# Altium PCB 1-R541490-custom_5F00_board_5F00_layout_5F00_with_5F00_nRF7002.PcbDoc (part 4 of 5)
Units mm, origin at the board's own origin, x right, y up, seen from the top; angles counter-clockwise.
Board outline 180 x 80 mm, 6 copper layers (Top Layer, GND 1, Signal 1, POWER, GND 2, Bottom Layer), stack 1.609 mm thick; 321 components, 275 nets, 828 pads, 1164 vias.
Unrouted connection lines stored in the file: 746.
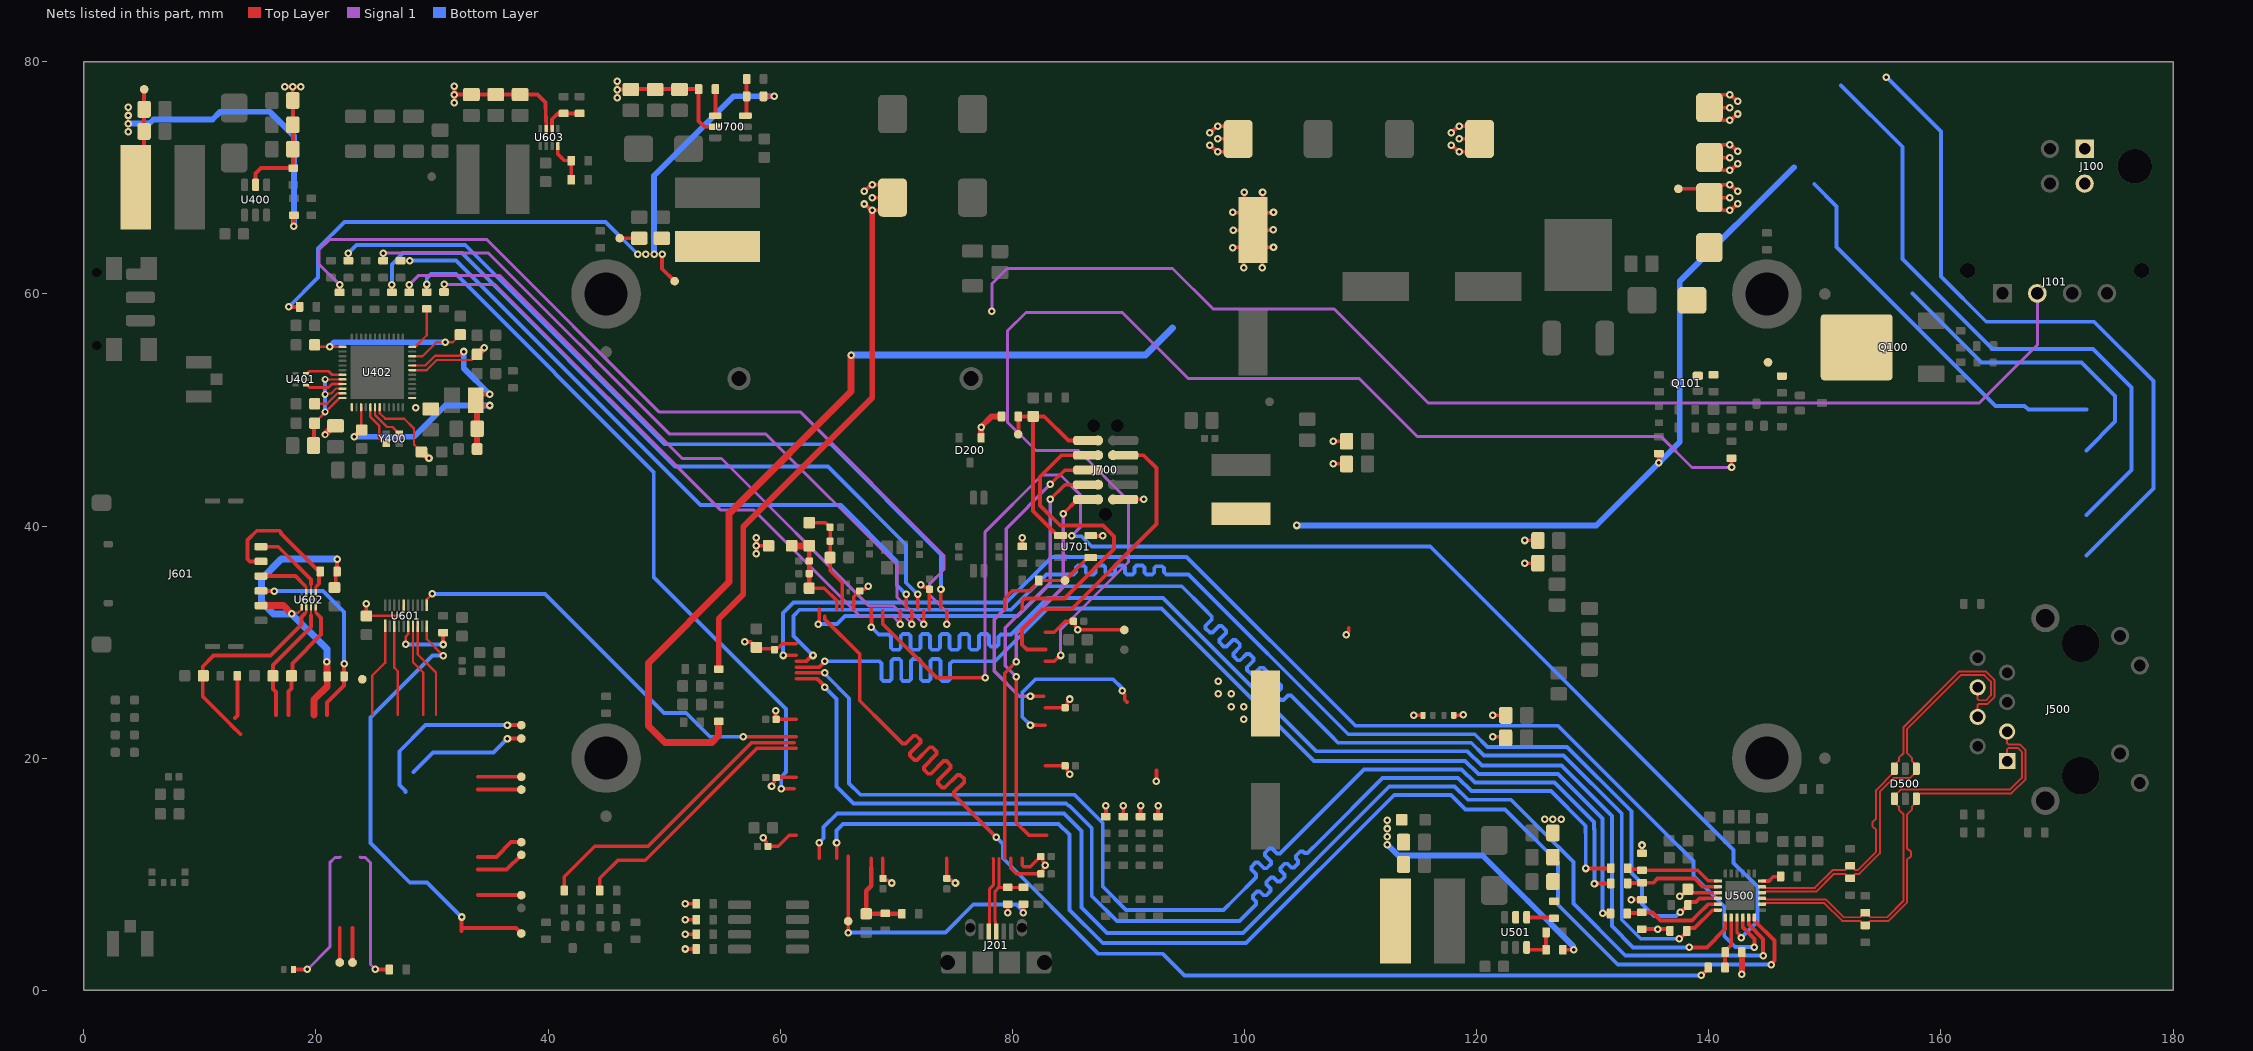
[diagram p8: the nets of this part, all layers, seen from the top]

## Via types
v1: diameter 0.65, hole 0.3, Top Layer to Bottom Layer, tented both sides, 675 vias
v2: diameter 0.7, hole 0.3, Top Layer to Bottom Layer, tented both sides, 462 vias
v3: diameter 0.6, hole 0.3, Top Layer to Bottom Layer, 16 vias
v4: diameter 0.6, hole 0.3, Top Layer to Bottom Layer, tented both sides, 7 vias
v5: diameter 0.6, hole 0.3, Top Layer to Bottom Layer, tented bottom, 4 vias

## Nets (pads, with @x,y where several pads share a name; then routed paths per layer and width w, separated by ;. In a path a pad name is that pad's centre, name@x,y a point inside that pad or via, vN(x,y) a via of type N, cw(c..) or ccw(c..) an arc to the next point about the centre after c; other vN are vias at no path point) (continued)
NetR416_1: R416.1 U402.36 | length 3.9
  Top Layer w0.2: U402.36@28.294,55.437 28.544,55.437 29.544,56.437 R416.1@29.544,58.712
NetR501_1: R501.1 R511.2 U500.11 | length 8.7
  Top Layer w0.3: 139.923,7.422 U500.11@140.778,7.422
  Top Layer w0.335: R511.2@132.978,6.622 133.028,6.672 134.168,6.672 R501.1@134.218,6.722 135.148,6.722 135.848,6.022 138.54,6.022 139.073,6.555 139.923,7.405
NetR502_1: R502.1 R508.2 U500.8 | length 8.2
  Top Layer w0.3: 139.487,8.923 U500.8@140.778,8.923
  Top Layer w0.335: R508.2@133.003,9.222 133.028,9.247 134.218,9.247 R502.1@134.243,9.273 135.225,9.273 135.575,9.622 138.787,9.622 139.469,8.94 139.487,8.94
NetR503_1: R503.1 R509.2 U500.7 | length 8.2
  Top Layer w0.3: 139.045,10.347 139.966,9.427 U500.7@140.773,9.427
  Top Layer w0.335: R509.2@133.003,10.522 133.003,10.505 133.073,10.435 134.156,10.435 R503.1@134.243,10.347 139.045,10.347
NetR510_2: R510.2 R512.1 U500.14 | length 4.6
  Top Layer w0.3: R512.1@141.395,1.86 R512.1@141.395,1.96 R512.1@141.4,1.965 ; R510.2@141.4,3.285 R510.2@141.405,3.29 R510.2@141.405,3.39 ; 141.928,3.913 U500.14@141.928,6.273
  Top Layer w0.335: R512.1@141.4,1.965 R510.2@141.4,3.285 ; R510.2@141.405,3.39 141.928,3.913
NetR513_2: R513.2 U500.24 | length 1.8
  Top Layer w0.335: U500.24@144.578,9.423 145.178,9.423 145.547,9.791 146.147,9.791 R513.2@146.178,9.822
NetR516_1: R516.1 U501.4 | length 2.4
  Top Layer w0.335: U501.4@124.309,6.35 124.375,6.285 126.602,6.285 R516.1@126.667,6.219
NetR517_1: R517.1 R520.2 U501.3 | length 3.3
  Top Layer w0.335: U501.3@124.338,3.621 124.309,3.65 124.309,3.632 124.442,3.5 R517.1@125.975,3.5 R520.2@125.975,5
NetR600_1: R600.1 | length 12.3
  Top Layer w0.335: R600.1@18.075,1.8 v1(19.271,1.8)
  Signal 1 w0.256: v1(19.271,1.8) 21.2,3.729 21.2,11 21.648,11.448 22.052,11.448 22.1,11.496
NetR602_2: R602.2 | length 3.8
  Top Layer w0.335: 13.018,23.45 13.25,23.683 13.238,23.695 13.238,27.087 R602.2@13.225,27.1
NetR603_2: R603.2 | length 11.7
  Top Layer w0.335: v1(25.129,1.8) R603.2@26.325,1.8
  Signal 1 w0.256: 23.8,11.496 23.86,11.436 24.264,11.436 24.7,11 24.7,2.229 v1(25.129,1.8)
NetR606_1: R606.1 U601.6 | length 5.8
  Top Layer w0.2: v1(27.75,29.8) 27.75,30.49 27.96,30.7 U601.6@27.96,31.37
  Top Layer w0.335: v1(30.96,29.797) R606.1@30.96,30.721
  Bottom Layer w0.335: v1(27.75,29.8) 27.752,29.798 30.959,29.798 v1(30.96,29.797)
NetR613_1: R613.1 R616.2 U603.8 | length 3.7
  Top Layer w0.3: U603.8@40.844,72.736 40.844,72.05 41.4,71.494 41.976,71.494 R616.2@41.994,71.476 R613.1@41.994,69.836
NetR614_1: R614.1 R615.2 U603.2 | length 3.4
  Top Layer w0.335: U603.2@40.344,74.216 40.344,75.051 40.844,75.551 R615.2@41.338,75.551 R614.1@42.719,75.551
NetR718_1: R718.1 U700.4 | length 2.3
  Top Layer w0.335: U700.4@54.35,75.35 54.415,75.415 R718.1@54.415,77.643
NetR719_1: R719.1 R722.2 U700.3 | length 3.2
  Top Layer w0.335: U700.3@57.05,75.35 57.079,75.379 57.079,78.494 R722.2@57.108,78.523
NetR821_1: 
NetR822_2: 
NetTP600_1: TP600.1 | length 3.7
  Top Layer w0.335: 33.975,8.2 TP600.1@37.7,8.2
NetTP603_1: TP603.1
NetTP604_1: TP604.1 | length 3.7
  Top Layer w0.335: 33.975,18.4 TP604.1@37.7,18.4
NetTP605_1: TP605.1 | length 3.7
  Top Layer w0.335: 33.975,17.3 TP605.1@37.7,17.3
NetTP606_1: TP606.1 | length 3
  Top Layer w0.335: TP606.1@23.15,2.4 23.15,5.37
NetTP607_1: TP607.1 | length 3
  Top Layer w0.335: TP607.1@22.05,2.4 22.05,5.37
NetTP608_1: TP608.1 | length 4.3
  Top Layer w0.335: 33.975,11.5 35.557,11.5 36.822,12.765 37.692,12.765 TP608.1@37.7,12.773
NetTP609_1: TP609.1 | length 4.3
  Top Layer w0.335: 33.975,10.4 36.427,10.4 TP609.1@37.7,11.673
NetTP610_1: TP610.1 | length 15.1
  Top Layer w0.335: v1(36.504,22.85) TP610.1@37.7,22.85
  Bottom Layer w0.335: 27.704,17.1 27.704,17.185 27.2,17.689 27.2,20.598 29.452,22.85 v1(36.504,22.85)
NetTP611_1: TP611.1 | length 10.5
  Top Layer w0.335: v1(36.504,21.696) TP611.1@37.7,21.696
  Bottom Layer w0.335: 28.396,18.8 30.096,20.5 35.308,20.5 v1(36.504,21.696)
NetU402_17: U402.17 Y400.3 | length 3.8
  Top Layer w0.2: U402.17@24.694,50.237 24.694,49.395 25.469,48.621 25.469,47.559 25.765,47.263 25.869,47.263 Y400.3@26.044,47.088
NetU402_18: U402.18 Y400.1 | length 3.4
  Top Layer w0.2: U402.18@25.094,50.237 25.094,49.561 26.118,48.537 26.594,48.537 Y400.1@27.194,47.937
nRST: C701.2 J700.10 R716.1 TP202.1 U500.15 U701.1 | length 138.7
  Top Layer w0.3: 68.85,32.699 68.85,31.561 73.461,26.95 v1(77.658,26.95) ; U500.15@142.428,6.273 142.428,5.017 142.8,4.645 v1(142.8,4.55)
  Top Layer w0.335: TP202.1@80.513,47.9 80.513,49.435 R716.1@80.515,49.437 ; R716.1@80.523,49.442 C701.2@81.792,49.442 ; C701.2@81.8,49.437 81.779,49.416 81.779,41.292 83.764,39.307 84.001,39.307 U701.1@84.141,39.167 ; C701.2@81.808,49.442 82.746,49.442 84.827,47.361 J700.10@86.257,47.361 ; U701.1@84.149,39.175 84.161,39.162 85.087,39.162 v1@85.107,39.142
  Signal 1 w0.256: v1(77.658,26.95) 77.658,39.508 82.55,44.4 84.15,44.4 85.857,42.693 85.857,39.893 v1(85.115,39.15)
  Bottom Layer w0.335: v1(85.115,39.15) 85.14,39.125 85.942,39.125 86.842,38.225 116.001,38.225 142.128,12.098 142.128,10.986 144.178,8.936 144.178,5.928 v1(142.8,4.55)
NTC: J101.2 | length 104.3
  Top Layer w0.335: v1(78.225,58.521) v1@78.236,58.521
  Signal 1 w0.256: v1(78.225,58.521) 78.225,60.861 79.564,62.2 93.8,62.2 97.3,58.7 107.721,58.7 115.821,50.6 163.3,50.6 168.3,55.6 J101.2@168.3,60.05
OFF_bt: R119.2 | length 107.8
  Top Layer w0.3: 82.838,28.35 83.606,28.35 84.106,28.85 v1(84.161,28.85)
  Top Layer w0.335: v1@141.958,45.05 R119.2@141.958,45.849
  Signal 1 w0.256: v1(84.161,28.85) 84.151,28.86 84.151,31.051 90,36.9 90,42.189 85.689,46.5 82.036,46.5 79.564,48.972 79.564,56.797 81.167,58.4 89.47,58.4 95.17,52.7 109.9,52.7 114.904,47.696 135.9,47.696 138.549,45.048 v1(141.956,45.048)
OUT1+:  | length 54
  Bottom Layer w0.335: 151.403,77.967 156.694,72.676 156.694,63.006 164.45,55.25 173.1,55.25 176.4,51.95 176.4,44.825 172.525,40.95
OUT1-:  | length 58.6
  Bottom Layer w0.335: v1@155.3,78.7 160,74 160,61.5 163.9,57.6 173.2,57.6 178.3,52.5 178.3,43.225 172.525,37.45
  other v1: 155.285,78.685
OUT2+:  | length 33.5
  Bottom Layer w0.335: 149.085,69.455 151,67.54 151,64.048 164.704,50.344 167.206,50.344 167.525,50.026 172.525,50.026
OUT2-:  | length 26.8
  Bottom Layer w0.335: 157.543,60.044 163.486,54.1 172.1,54.1 175,51.2 175,49.001 172.525,46.526
PALDO: C416.2 C417.2 U402.8 U402.10 U402.12 | length 11.3
  Top Layer w0.17: v4(20.794,51.337) 20.876,51.42 21.302,51.42 21.719,51.837 U402.10@22.294,51.837 ; v4(20.794,52.637) U402.8@22.294,52.637
  Top Layer w0.2: C416.2@19.894,48.837 19.894,48.894 20.794,49.794 v4(20.794,49.837) 20.836,49.837 22.036,51.037 U402.12@22.294,51.037
  Top Layer w0.335: C417.2@19.794,46.937 19.844,46.987 19.844,48.787 C416.2@19.894,48.837
  Bottom Layer w0.335: v4(20.794,49.837) v4(20.794,51.337) v4(20.794,52.637)
PVDD: C302.1 C304.2 C305.2 C306.2 C307.2 C308.2 C309.2 L300.2 | length 6.9
  Top Layer w0.3: v1(107.652,45.35) C308.2@108.79,45.35 ; v1(107.652,47.3) C307.2@108.79,47.3 ; v1(121.369,21.863) 122.386,21.863 C305.2@122.491,21.757 ; v1(121.369,23.69) C306.2@122.507,23.69 ; v1(124.137,36.803) C309.2@125.275,36.803 ; v1(124.137,38.757) C304.2@125.275,38.757
  other v1: 99.95,23.35 98.85,24.45 99.95,24.45 97.75,25.55 98.85,25.55 97.75,26.65
PWRIOVDD: C407.2 C410.2 U402.1 U402.34 | length 17.5
  Top Layer w0.2: C407.2@19.894,55.612 20.069,55.437 v1(21.182,55.437) U402.1@22.294,55.437 ; U402.34@28.294,54.637 29.178,54.637 30.378,55.837 v1(31.144,55.837) 31.794,55.837 32.044,56.087 32.044,56.089 C410.2@32.444,56.487 C410.2@32.444,56.487
  Bottom Layer w0.5: v1(21.182,55.437) 21.582,55.837 v1(31.144,55.837)
PWRKEY: R609.1 | length 22.6
  Top Layer w0.3: R609.1@44.451,8.6 44.451,9.65 46.024,11.223 48.37,11.223 57.997,20.85 61.362,20.85
QSPI_CLK/SPI_CLK: R405.2 | length 53.2
  Top Layer w0.2: R405.2@31.044,60.166 R405.2@31.046,60.164 v1(31.046,60.814)
  Top Layer w0.3: v1(70.35,31.561) 70.35,32.699
  Signal 1 w0.256: v1(31.046,60.814) 35.426,60.814 54.84,41.4 57.7,41.4 66.9,32.2 69.711,32.2 v1(70.35,31.561)
QSPI_DATA0/SPI_MOSI: R411.2 | length 57.9
  Top Layer w0.2: R411.2@28.044,60.137 v1(28.044,60.787)
  Top Layer w0.3: v1(71.35,31.561) 71.35,32.699
  Signal 1 w0.256: v1(28.044,60.787) 28.856,61.6 35.79,61.6 51.56,45.83 54.945,45.83 67.675,33.1 69.811,33.1 v1(71.35,31.561)
QSPI_DATA1/SPI_MISO: R415.2 | length 57.8
  Top Layer w0.2: R415.2@27.294,62.862 v1(28.094,62.862)
  Top Layer w0.3: 70.85,32.977 v1(70.85,34.115)
  Bottom Layer w0.335: v1(28.094,62.862) 32.073,62.862 53.136,41.8 65.229,41.8 70.038,36.991 70.038,34.927 v1(70.85,34.115)
QSPI_DATA2: R410.2 | length 63.3
  Top Layer w0.2: R410.2@26.544,60.137 v1(26.544,60.787)
  Top Layer w0.3: 71.85,32.977 v1(71.85,34.115)
  Bottom Layer w0.335: v1(26.544,60.787) 26.544,62.544 27.512,63.512 32.569,63.512 50.946,45.135 64.109,45.135 70.85,38.394 70.85,35.115 v1(71.85,34.115)
QSPI_DATA3: R414.2 | length 63.2
  Top Layer w0.2: R414.2@25.794,62.862 v1(25.794,63.512)
  Top Layer w0.3: v1(72.35,31.561) 72.35,32.699
  Signal 1 w0.256: v1(25.794,63.512) 34.868,63.512 50.43,47.95 58.742,47.95 70.053,36.639 70.053,33.858 v1(72.35,31.561)
QSPI_SS/SPI_SS: R416.2 | length 61.3
  Top Layer w0.2: R416.2@29.544,60.162 v1(29.544,60.812)
  Top Layer w0.3: v1(60.085,17.35) 61.223,17.35
  Bottom Layer w0.335: v1(29.544,60.812) 29.544,61.344 29.9,61.7 32.07,61.7 49.1,44.67 49.1,35.625 60.5,24.225 60.5,18.816 60.085,18.401 v1(60.085,17.35)
R1: U601.1 | length 8.1
  Top Layer w0.2: 24.85,23.73 24.85,27.115 25.96,28.225 U601.1@25.96,31.42
RD_N: D500.4 J500.6 R504.2 U500.22 | length 38
  Top Layer w0.17: U500.22@144.578,8.423 144.643,8.487 144.918,8.487 144.943,8.513 149.261,8.513 150.786,10.037 151.739,10.037 151.846,9.93 151.846,9.887 152.085,9.647 R504.2@152.178,9.647 152.271,9.647 152.51,9.887 152.51,9.93 152.618,10.037 152.974,10.037 154.73,11.793 154.73,17.113 155.932,18.315 157.346,18.315 157.881,18.85 D500.4@157.881,19.1 157.881,19.385 157.493,19.774 157.493,20.034 157.092,20.434 157.092,22.532 161.717,27.157 163.743,27.157 164.3,26.6 164.3,25.41 163.885,24.995 163.26,24.995 163.16,25.095 J500.6@163.16,26.105
RD_P: D500.6 J500.4 R505.2 U500.23 | length 37.9
  Top Layer w0.17: U500.23@144.578,8.923 144.643,8.858 144.918,8.858 144.943,8.832 149.128,8.832 150.653,10.357 151.739,10.357 151.846,10.465 151.846,10.508 152.085,10.747 R505.2@152.178,10.747 152.271,10.747 152.51,10.508 152.51,10.465 152.618,10.357 152.842,10.357 154.41,11.926 154.41,13.754 154.41,13.839 154.274,13.975 154.243,13.975 154.107,14.111 154.107,14.517 154.243,14.653 154.274,14.653 154.41,14.789 154.41,15.46 154.41,17.245 155.981,18.816 D500.6@155.981,19.1 155.981,19.385 156.373,19.777 156.373,20.034 156.772,20.433 156.772,22.665 161.585,27.477 163.875,27.477 164.62,26.733 164.62,25.277 164.018,24.675 163.26,24.675 163.16,24.575 J500.4@163.16,23.565
RESET_N: R607.1 | length 25.8
  Top Layer w0.3: R607.1@41.401,8.6 41.401,9.773 44.028,12.4 48.613,12.4 57.563,21.35 61.223,21.35
RMII_CRS_DV: R511.1 | length 101
  Top Layer w0.3: 61.362,27.85 63.333,27.85 63.35,27.867
  Top Layer w0.335: 63.35,27.867 63.367,27.867 v1(63.85,28.35) ; v1(130.85,6.65) 130.864,6.636 131.514,6.636 R511.1@131.528,6.622
  Bottom Layer w0.335: v1@63.854,28.35 67.532,28.35 68.542,28.35 68.738,28.154 68.738,26.824 68.907,26.656 69.412,26.656 69.581,26.824 69.581,28.373 69.749,28.541 70.255,28.541 70.424,28.373 70.424,26.824 70.592,26.656 71.098,26.656 71.266,26.824 71.266,28.373 71.435,28.541 71.941,28.541 72.109,28.373 72.109,26.824 72.278,26.656 72.783,26.656 72.952,26.824 72.952,28.373 73.121,28.541 73.626,28.541 73.795,28.373 73.795,26.824 73.963,26.656 74.469,26.656 74.638,26.824 74.638,28.154 74.834,28.35 77.87,28.35 78.5,28.35 83.05,32.9 92.852,32.9 105.981,19.772 119.011,19.772 120.153,18.63 127.013,18.63 130.85,14.793 v1(130.85,6.65)
RMII_MDC: U500.13 | length 109.6
  Top Layer w0.3: 67.85,32 67.85,32.838 ; 141.411,5.278 141.428,5.296 U500.13@141.428,6.273
  Top Layer w0.335: v1(67.85,31.3) 67.85,32 ; v1(138.3,3.7) 139.833,3.7 141.411,5.278
  Bottom Layer w0.335: v1(67.85,31.3) 68.336,30.814 68.5,30.65 69.347,30.65 69.543,30.454 69.543,29.514 69.711,29.345 70.217,29.345 70.386,29.514 70.386,30.533 70.554,30.702 71.06,30.702 71.228,30.533 71.228,29.514 71.397,29.345 71.903,29.345 72.071,29.514 72.071,30.533 72.24,30.702 72.745,30.702 72.914,30.533 72.914,29.514 73.082,29.345 73.588,29.345 73.757,29.514 73.757,30.533 73.925,30.702 74.431,30.702 74.6,30.533 74.6,29.514 74.768,29.345 75.274,29.345 75.442,29.514 75.442,30.533 75.611,30.702 76.117,30.702 76.285,30.533 76.285,29.514 76.454,29.345 76.959,29.345 77.128,29.514 77.128,30.533 77.296,30.702 77.802,30.702 77.971,30.533 77.971,29.787 78.139,29.618 78.645,29.618 78.813,29.787 78.813,30.454 79.01,30.65 79.192,30.65 79.889,30.65 83.039,33.8 92.992,33.8 106.196,20.596 119.226,20.596 120.457,19.365 127.318,19.365 131.65,15.033 131.65,5.534 133.484,3.7 v1(138.3,3.7)
RMII_MDIO: R500.2 U500.12 | length 109.7
  Top Layer w0.3: v1(63.28,31.56) 63.28,31.655 63.35,31.725 63.35,32.838 ; 140.308,6.905 140.325,6.923 U500.12@140.778,6.923
  Top Layer w0.335: v1(137.45,4.45) 137.531,4.45 138.103,5.022 R500.2@138.103,5.122 ; R500.2@138.103,5.222 138.261,5.38 138.783,5.38 140.308,6.905
  Bottom Layer w0.335: v1(63.28,31.56) 64.889,31.56 65.579,32.25 67.56,32.25 67.563,32.253 76.637,32.253 76.64,32.25 80.45,32.25 83.011,34.811 94.589,34.811 96.465,32.935 97.179,32.22 97.179,31.943 96.653,31.417 96.653,31.178 97.01,30.821 97.249,30.821 97.802,31.374 98.041,31.374 98.398,31.017 98.398,30.778 97.844,30.225 97.844,29.986 98.202,29.629 98.44,29.629 98.994,30.182 99.232,30.182 99.59,29.825 99.59,29.586 99.036,29.033 99.036,28.794 99.394,28.437 99.632,28.437 100.186,28.99 100.424,28.99 100.782,28.633 100.782,28.395 100.228,27.841 100.228,27.603 100.586,27.245 100.824,27.245 101.378,27.799 101.616,27.799 101.974,27.441 101.974,27.203 101.42,26.649 101.42,26.411 101.778,26.053 102.016,26.053 102.57,26.607 102.808,26.607 103.166,26.249 103.166,26.011 102.769,25.614 102.769,25.375 103.126,25.018 103.365,25.018 103.735,25.388 104.012,25.388 107.373,22.026 108.069,21.33 119.53,21.33 120.626,20.235 127.487,20.235 132.5,15.222 132.5,6.084 134.134,4.45 v1(137.45,4.45)
RMII_REF_CLK: R512.2 | length 104.7
  Top Layer w0.3: 63.85,31.975 63.85,32.225
  Top Layer w0.335: 63.867,31.975 63.867,31.957 66.85,28.975 66.85,24.95 69.2,22.6 70.537,21.263 70.814,21.263 71.484,21.933 71.722,21.933 72.08,21.576 72.08,21.337 71.194,20.452 71.194,20.213 71.552,19.856 71.79,19.856 72.88,20.945 73.118,20.945 73.476,20.588 73.476,20.349 72.386,19.26 72.386,19.021 72.744,18.664 72.982,18.664 74.072,19.753 74.31,19.753 74.667,19.396 74.667,19.157 73.578,18.068 73.578,17.829 73.936,17.472 74.174,17.472 75.263,18.561 75.502,18.561 75.859,18.204 75.859,17.965 74.986,17.092 74.986,16.814 75.7,16.1 v1(78.6,13.2) ; v1(139.34,1.29) 139.375,1.29 139.945,1.86 R512.2@139.945,1.96
  Bottom Layer w0.335: v1(78.6,13.2) 79.192,12.608 79.192,11.378 87.42,3.15 92.96,3.15 94.82,1.29 v1(139.34,1.29)
RMII_RX_ER: R514.2 U500.10 | length 109.5
  Top Layer w0.3: 61.362,28.35 62.24,28.35 ; 139.666,7.923 U500.10@140.778,7.923
  Top Layer w0.335: 62.275,28.385 62.74,28.85 v1(62.825,28.85) ; v1(137.531,6.722) 137.592,6.722 137.96,7.09 138.046,7.09 138.203,7.248 R514.2@138.203,7.333 ; R514.2@138.203,7.448 138.361,7.605 138.879,7.605 139.179,7.905 139.666,7.905
  Bottom Layer w0.335: v1(62.825,28.85) 61.138,30.537 61.138,32.25 61.676,32.788 79.888,32.788 82.938,35.838 85.115,35.838 85.282,35.838 85.478,36.034 85.478,36.438 85.647,36.607 86.152,36.607 86.321,36.438 86.321,35.989 86.49,35.82 86.995,35.82 87.164,35.989 87.164,36.438 87.332,36.607 87.838,36.607 88.007,36.438 88.007,35.989 88.175,35.82 88.681,35.82 88.849,35.989 88.849,36.438 89.018,36.607 89.524,36.607 89.692,36.438 89.692,35.989 89.861,35.82 90.366,35.82 90.535,35.989 90.535,36.438 90.704,36.607 91.209,36.607 91.378,36.438 91.378,35.989 91.546,35.82 92.052,35.82 92.221,35.989 92.221,36.373 92.389,36.542 92.895,36.542 93.063,36.373 93.063,36.034 93.259,35.838 94.434,35.838 95.162,35.838 108.935,22.065 119.835,22.065 120.929,20.971 127.79,20.971 133.329,15.432 133.329,10.114 134.243,9.2 134.243,7.437 135.28,6.4 137.177,6.4 137.499,6.722 v1(137.531,6.722)
RMII_RXD0: R508.1 | length 101.5
  Top Layer w0.3: 61.362,27.35 v1(63.85,27.35)
  Top Layer w0.335: v1(130.15,9.2) 130.161,9.211 131.542,9.211 R508.1@131.553,9.222
  Bottom Layer w0.335: v1(63.85,27.35) 63.85,27.265 64.008,27.107 64.008,27.101 65.939,25.169 65.939,17.811 66.9,16.85 85.35,16.85 87.782,14.418 87.782,8.955 89.801,6.936 98.197,6.936 99.113,7.852 100.994,9.732 100.994,10.009 100.59,10.412 100.59,10.651 100.948,11.008 101.186,11.008 101.678,10.517 101.916,10.517 102.274,10.874 102.274,11.113 101.772,11.614 101.772,11.853 102.13,12.21 102.368,12.21 102.781,11.797 103.059,11.797 103.773,12.512 110.298,19.037 118.706,19.037 119.848,17.895 126.709,17.895 130.115,14.489 130.115,13.882 ; v1(130.15,9.2) 130.15,13.867
RMII_RXD1: R509.1 | length 101.5
  Top Layer w0.3: 61.362,26.85 63.168,26.85 63.185,26.833
  Top Layer w0.335: 63.185,26.833 63.203,26.833 63.85,26.185 v1(63.85,26.1) ; v1(129.4,10.5) 129.411,10.511 131.542,10.511 R509.1@131.553,10.522
  Bottom Layer w0.335: v1(63.85,26.1) 64.85,25.1 64.85,17.576 66.311,16.115 84.624,16.115 84.832,15.907 84.914,15.907 86.842,13.979 86.842,8.145 89.027,5.96 99.56,5.96 100.865,7.265 100.984,7.384 100.984,7.661 100.715,7.929 100.715,8.168 101.073,8.525 101.311,8.525 101.643,8.194 101.881,8.194 102.239,8.551 102.239,8.79 101.907,9.121 101.907,9.36 102.265,9.717 102.503,9.717 102.835,9.386 103.073,9.386 103.43,9.743 103.43,9.982 103.099,10.313 103.099,10.551 103.456,10.909 103.695,10.909 104.026,10.577 104.265,10.577 104.622,10.935 104.622,11.173 104.439,11.356 104.439,11.595 104.797,11.952 105.035,11.952 105.155,11.832 105.432,11.832 106.57,12.97 111.902,18.302 118.402,18.302 119.544,17.16 126.405,17.16 129.38,14.185 129.38,13.578 129.4,13.558 v1(129.4,10.5)
RMII_TX_EN: U500.16 | length 109.6
  Top Layer w0.3: v1(60.27,28.85) 61.362,28.85 ; U500.16@142.928,6.273 142.928,5.445 142.949,5.424 142.949,5.399
  Top Layer w0.335: 142.949,5.399 143.928,4.42 v1(143.928,3.722)
  Bottom Layer w0.335: v1(60.27,28.85) 60.224,28.896 60.224,32.508 61.138,33.423 79.473,33.423 83.4,37.35 95.005,37.35 109.555,22.8 120.997,22.8 121,22.797 121.739,22.797 121.742,22.8 127,22.8 136.009,13.791 136.026,13.791 138.676,11.141 138.676,9.875 141.327,7.224 141.327,4.673 142.278,3.722 v1(143.928,3.722)
RMII_TXD0: U500.17 | length 109.6
  Top Layer w0.3: 63.35,11.362 v1(63.35,12.713) ; 143.428,5.677 143.428,6.029 U500.17@143.428,6.273
  Top Layer w0.335: 143.446,5.677 143.446,5.659 144.678,4.427 v1(144.678,2.997)
  Bottom Layer w0.335: v1(63.35,12.713) 63.741,13.104 63.741,14.081 64.91,15.25 84.45,15.25 85.971,13.729 85.971,7.129 88.15,4.95 99.855,4.95 112.473,17.567 118.098,17.567 119.239,16.426 122.949,16.426 124.975,14.4 124.975,14.375 125.498,13.852 125.523,13.852 128.328,11.047 128.328,7.472 132.803,2.997 v1(144.678,2.997)
RMII_TXD1: U500.18 | length 109.6
  Top Layer w0.3: 64.85,11.362 v1(64.85,12.713) ; U500.18@143.928,6.273 143.928,6.032 U500.18@143.946,6.015
  Top Layer w0.335: U500.18@143.946,5.998 145.643,4.3 145.643,2.573 145.378,2.308 v1(145.378,2.222)
  Bottom Layer w0.335: v1(64.85,12.713) 64.85,13.774 65.418,14.342 83.99,14.342 84.914,13.418 84.914,6.936 87.782,4.068 100.139,4.068 112.904,16.833 117.793,16.833 119.028,15.598 122.442,15.598 127,11.04 127,7.38 132.158,2.222 v1(145.378,2.222)
RTS: U601.3 | length 7.8
  Top Layer w0.2: U601.3@26.76,31.37 26.76,27.79 27.05,27.5 27.05,23.73
RXD: U601.8 | length 8.3
  Top Layer w0.2: U601.8@28.76,31.37 28.76,28.965 30.35,27.375 30.35,23.73
SIM_C_CLK: J601.C3 U602.2 | length 6.6
  Top Layer w0.2: 19.568,35.012 19.568,35.007 19.575,35 U602.2@19.575,34.292
  Top Layer w0.335: J601.C3@15.265,38.225 15.27,38.22 16.755,38.22 19.575,35.4 19.575,35.02
SIM_C_DATA: J601.C7 R611.2 U602.1 | length 12.6
  Top Layer w0.2: U602.1@19.975,34.292 19.975,34.758 20.112,34.895
  Top Layer w0.335: J601.C7@15.265,36.955 14.301,36.955 14.104,37.152 14.104,38.8 14.904,39.6 16.583,39.6 ; 16.75,39.6 16.85,39.6 17.007,39.443 17.007,39.343 20.27,36.08 20.27,35.054 20.112,34.895
SIM_C_RST: J601.C2 U602.3 | length 4.8
  Top Layer w0.2: 19.038,34.895 19.175,34.758 U602.3@19.175,34.292
  Top Layer w0.335: J601.C2@15.265,35.685 18.248,35.685 19.038,34.895
SIM_CLK: C611.2 U602.7 | length 10.7
  Top Layer w0.2: 19.575,32.313 U602.7@19.575,33.022
  Top Layer w0.335: 16.55,23.73 16.55,25.7 16.3,25.95 16.3,28.036 19.575,31.311 19.575,32.1 19.568,32.107 19.568,32.301
sim_connector.SIM_DATA: C610.2 U602.8 | length 10.7
  Top Layer w0.2: U602.8@19.975,33.022 19.975,32.555 20.112,32.418
  Top Layer w0.335: 17.65,23.73 17.65,25.75 17.9,26 C610.2@17.9,27.1 17.966,27.166 17.966,28.172 20.454,30.66 20.454,32.076 20.112,32.418
sim_connector.SIM_PRES: J601.C6 R612.2 | length 16.9
  Top Layer w0.335: J601.C6@15.5,34.4 v1(16.424,34.4) ; 20.95,23.73 20.95,24.8 22.425,26.275 R612.2@22.425,27.05 ; R612.2@22.425,27.325 v1(22.425,28.123)
  Bottom Layer w0.335: v1(16.424,34.4) 20.608,34.4 22.425,32.583 v1(22.425,28.123)
sim_connector.SIM_RST: C612.2 U602.6 | length 18.9
  Top Layer w0.2: 19.038,32.418 19.175,32.555 U602.6@19.175,33.022
  Top Layer w0.335: 13.496,22.063 12.771,22.788 12.765,22.788 12.532,23.02 12.532,23.026 10.253,25.306 10.253,27.917 11.18,28.844 16.095,28.844 18.762,31.512 18.762,32.157 19.031,32.425
sim_connector.SIM_VDD: C613.2 J601.C1 R611.1 R612.1 U602.5 | length 29.3
  Top Layer w0.2: v1(17.912,32.438) 17.998,32.524 18.467,32.524 18.775,32.832 U602.5@18.775,33.022
  Top Layer w0.335: C613.2@21.6,34.7 21.709,34.809 21.709,35.97 R611.1@21.819,36.08 ; R611.1@21.819,36.105 v1(21.819,37.152)
  Top Layer w0.6: J601.C1@15.265,33.145 17.191,33.145 17.898,32.438 v1(17.912,32.438) ; 19.85,23.73 19.85,25.05 20.976,26.176 R612.1@20.975,27.05 ; v1(20.95,28.3) 20.96,28.29 20.96,27.065 R612.1@20.975,27.05
  Bottom Layer w0.6: v1(20.95,28.3) 20.95,29.4 v1(17.912,32.438) 16.347,32.438 15.3,33.485 15.3,35.438 17.014,37.152 v1(21.819,37.152)
STANDBY: 
SW_CTRL0: R412.2 | length 67.6
  Top Layer w0.2: R412.2@22.794,62.862 v1(22.794,63.512)
  Top Layer w0.3: 73.85,32.977 v1(73.85,34.55)
  Bottom Layer w0.335: v1(22.794,63.512) 23.481,64.2 32.864,64.2 50.014,47.05 64.359,47.05 73.85,37.559 v1(73.85,34.55)
SW_CTRL1: R404.2 | length 78.1
  Top Layer w0.2: R404.2@22.044,60.137 v1(22.044,60.787)
  Top Layer w0.3: v1(74.35,31.561) 74.35,32.699
  Signal 1 w0.256: v1(22.044,60.787) 20.276,62.556 20.276,63.792 21.184,64.7 34.696,64.7 49.583,49.813 61.762,49.813 74.1,37.475 74.1,36.249 72.848,34.997 72.848,34.102 74.35,32.6 v1(74.35,31.561)
SXLDO: C415.2 U402.11 | length 2.8
  Top Layer w0.2: C415.2@19.894,50.537 20.964,50.537 21.864,51.437 U402.11@22.294,51.437
TCLK/SWCLK: J700.4 | length 36.1
  Top Layer w0.3: v1(80.35,27.029) 80.35,14.43 81.43,13.35 82.977,13.35 ; v1(83.274,42.294) 84.534,43.554 J700.4@85.922,43.554
  Signal 1 w0.3: v1(80.35,27.029) 79.4,27.979 79.4,31.238 83.274,35.112 v1(83.274,42.294)
TD_N: D500.3 J500.3 R506.1 U500.20 | length 39.4
  Top Layer w0.17: U500.20@144.578,7.422 144.643,7.487 144.918,7.487 144.943,7.512 149.953,7.512 151.486,5.98 153.039,5.98 153.146,5.873 153.146,5.829 153.385,5.59 R506.1@153.478,5.59 153.571,5.59 153.81,5.829 153.81,5.873 153.918,5.98 155.492,5.98 157.09,7.578 157.09,10.508 157.09,11.271 157.226,11.407 157.29,11.407 157.426,11.543 157.426,11.949 157.29,12.085 157.226,12.085 157.09,12.221 157.09,12.822 157.09,15.167 157.49,15.566 157.49,15.823 157.881,16.215 157.881,16.715 158.091,16.925 158.156,16.925 158.196,16.965 166.072,16.965 167.29,18.183 167.29,20.673 166.778,21.185 165.8,21.185 165.7,21.285 J500.3@165.7,22.295
TD_P: D500.1 J500.1 R507.1 U500.21 | length 39.5
  Top Layer w0.17: U500.21@144.578,7.923 144.643,7.858 144.918,7.858 144.943,7.832 150.086,7.832 151.618,6.3 153.039,6.3 153.146,6.407 153.146,6.451 153.385,6.69 R507.1@153.478,6.69 153.571,6.69 153.81,6.451 153.81,6.407 153.918,6.3 155.36,6.3 156.77,7.71 156.77,15.166 156.37,15.566 156.37,15.826 155.981,16.215 D500.1@155.981,16.5 155.981,16.75 156.516,17.285 165.94,17.285 166.97,18.315 166.97,20.54 166.645,20.865 165.8,20.865 165.7,20.765 J500.1@165.7,19.755
TDO/SWO: J700.6 | length 26.4
  Top Layer w0.3: v1(81.561,25.35) 82.699,25.35 ; v1(83.274,43.59) 84.508,44.824 J700.6@85.922,44.824
  Signal 1 w0.3: v1(81.561,25.35) 80.6,25.35 78.456,27.494 78.456,31.977 79.465,32.986 79.465,39.781 v1(83.274,43.59)
TMS/SWDIO: J700.2 | length 34.2
  Top Layer w0.3: 79.35,11.362 79.35,27.319 v1(80.35,28.319) ; v1(84.376,41.062) 84.386,41.062 85.612,42.289 J700.2@86.267,42.289
  Signal 1 w0.3: v1(80.35,28.319) 80.35,30.724 84.376,34.749 v1(84.376,41.062)
TXD: U601.7 | length 8
  Top Layer w0.2: U601.7@28.36,31.37 28.36,28.265 29.25,27.375 29.25,23.73
TXRF0: U401.1 U402.9 | length 3.2
  Top Layer w0.25: U401.1@19.282,52.1 19.444,51.937 21.094,51.937 21.394,52.237 U402.9@22.294,52.237
TXRF1: U401.3 U402.7 | length 3.2
  Top Layer w0.25: U401.3@19.282,53.175 19.444,53.337 21.094,53.337 21.394,53.037 U402.7@22.294,53.037
UART_RX: J700.8 | length 26.1
  Top Layer w0.335: 80.85,32.838 80.85,33.558 81.046,33.754 84.484,33.754 88.753,38.023 88.753,39.095 87.798,40.05 84.128,40.05 82.39,41.788 82.39,44.244 84.245,46.099 J700.8@86.264,46.099
UART_TX: J700.7 | length 26.7
  Top Layer w0.335: 82.838,29.35 81.246,29.35 80.825,29.771 80.825,31.075 82.588,32.838 85.08,32.838 92.405,40.163 92.405,44.997 91.303,46.099 J700.7@89.82,46.099
USB_N: J201.2 | length 6.5
  Top Layer w0.27: J201.2@77.95,5.075 78.015,5.14 78.015,5.939 78.04,5.964 78.04,8.745 78.365,9.07 78.365,11.347 78.35,11.362
USB_on: R203.1 TP204.1 | length 23.8
  Top Layer w0.3: v1@65.85,4.975 TP204.1@65.85,5.964 65.85,11.362 65.85,11.575
  Top Layer w0.335: v1@80.95,6.695 R203.1@80.95,7.425
  Bottom Layer w0.335: v1(65.848,4.973) 74.222,4.973 76.633,7.384 80.343,7.384 80.948,6.778 v1(80.948,6.693)
USB_P: J201.3 R201.2 R203.2 | length 8.6
  Top Layer w0.27: J201.3@78.6,5.075 78.535,5.14 78.535,5.939 78.51,5.964 78.51,8.55 78.835,8.875 ; 78.85,11.362 78.835,11.347 78.835,10.731 78.835,8.875 ; R203.2@80.95,8.875 R201.2@79.6,8.875 78.835,8.875
VBAT: D102.2 D104.2 D300.2 Q100.3 Q101.2 R106.2 R113.2 R207.2 TP102.1 | length 80.9
  Top Layer w0.3: v1(118.5,72.25) 119.448,72.25 D102.2@119.498,72.3 ; v1(118.5,73.35) 119.535,73.35 D102.2@119.548,73.364 ; v1(118.5,74.45) 119.547,74.45 D102.2@119.548,74.448
  Top Layer w0.35: v1(117.8,72.8) 117.875,72.8 118.425,72.25 v1(118.5,72.25) ; v1(117.8,73.9) 117.848,73.9 118.341,74.393 118.443,74.393 v1(118.5,74.45)
  Top Layer w0.6: R207.2@54.7,23.175 54.7,21.943 54.107,21.35 50.08,21.35 48.65,22.78 48.65,28.221 55.6,35.171 55.6,41.061 66.115,51.576 v1(66.115,54.724)
  Bottom Layer w0.6: v1(66.115,54.724) 91.461,54.724 93.8,57.064
VBAT_nRF: C404.2 C405.2 C408.2 C411.2 C418.2 C422.2 L400.2 R401.2 TP400.1 U402.13 U402.19 U402.25 U402.31 | length 48.9
  Top Layer w0.2: U402.19@25.494,50.237 25.494,49.727 25.984,49.237 27.619,49.237 28.454,48.402 28.454,47.027 28.694,46.787 28.694,46.785 C422.2@29.094,46.387 C422.2@29.094,46.387 ; U402.31@28.294,53.437 29.547,53.437 30.413,54.303 33.409,54.303 33.52,54.414 33.522,54.414 33.894,54.785 C408.2@33.894,54.787
  Top Layer w0.335: L400.2@4.475,69.2 5.2,69.925 C405.2@5.2,74 C404.2@5.2,75.9 TP400.1@5.2,77.626 ; v1(18.1,65.818) R401.2@18.1,66.775
  Top Layer w0.381: C411.2@29.567,50.365 C411.2@29.894,50.037
  Top Layer w0.5: C411.2@29.471,50.365 C411.2@29.567,50.365
  Top Layer w0.6: v4(20.794,47.887) 21.269,48.362 C418.2@21.694,48.637 ; C422.2@29.169,46.437 v1(29.742,45.83) ; C408.2@33.894,54.787 v1@34.5,55.362
  Bottom Layer w0.5: v1(3.815,74.671) 5.637,74.671 5.998,75.032 11.085,75.032 11.753,75.7 16.032,75.7 18.1,73.632 v1(18.1,65.818)
  other v1: 28.594,50.187 34.502,55.361 3.815,73.971 3.815,75.371 3.815,76.071
VBUSpr: C223.2 R202.1 R204.2 | length 8
  Top Layer w0.3: 67.85,10.55 67.85,11.362
  Top Layer w0.4: C223.2@67.375,6.6 R204.2@69.025,6.6 ; C223.2@67.4,6.6 67.4,8.575 67.85,9.025 67.85,10.55 ; R204.2@69.05,6.625 R204.2@69.15,6.625 ; R204.2@69.175,6.6 R202.1@70.475,6.6
VCC: C100.1 C401.1 C402.1 C403.2 C512.1 C513.1 C514.2 C615.1 C616.1 C617.2 C702.1 C703.1 C704.2 D100.1 D104.1 R400.2 R516.2 R718.2 TP100.1 U400.5 U501.5 U603.3 U700.5 | length 66.5
  Top Layer w0.3: v1(99.003,63.97) 99.033,64 102.467,64 v1(102.497,64.03) ; v1(99.017,65.47) 99.047,65.5 C100.1@100.75,65.5 ; v1@99.033,67 C100.1@100,67 ; v1(99.95,62.25) C100.1@99.95,63.154 ; v1(99.97,68.747) 99.97,66.28 C100.1@100.75,65.5 ; v1@101.5,62.283 v1(101.53,62.253) C100.1@101.53,63.154 ; v1@101.575,68.75 v1(101.55,68.75) 101.55,67.05 101.5,67 102.467,67 v1(102.497,67.03) ; v1(102.483,65.53) 102.453,65.5 C100.1@100.75,65.5 ; TP100.1@137.375,69.054 139.296,69.054 D104.1@140.05,68.3 ; D104.1@140.751,67.202 140.753,67.2 v1(141.8,67.2) ; D104.1@140.751,68.286 140.765,68.3 v1(141.8,68.3) ; D100.1@140.752,70.651 140.753,70.65 v1(141.8,70.65) ; D100.1@140.752,71.736 140.765,71.75 v1(141.8,71.75) ; D104.1@140.801,69.35 140.851,69.4 v1(141.8,69.4) ; D100.1@140.802,72.8 140.852,72.85 v1(141.8,72.85)
  Top Layer w0.335: U400.5@14.8,69.45 14.8,70.359 15.276,70.835 R400.2@18.043,70.835 18.026,70.852 18.026,76.652 C401.1@18.008,76.67 v1(18.008,77.845) ; v1(17.308,77.845) v1(18.008,77.845) ; v1(18.708,77.845) v1(18.008,77.845) ; v1(31.936,76.476) v1(31.936,77.176) ; v1(31.936,77.876) v1(31.936,77.176) ; U603.3@39.844,74.216 39.794,76.476 39.094,77.176 C617.2@37.594,77.176 C616.1@35.494,77.176 C615.1@33.394,77.176 v1(31.936,77.176) ; v1(45.955,76.908) v1(45.955,77.608) ; v1(45.955,78.308) v1(45.955,77.608) ; U700.5@54.35,74.4 53.476,74.4 52.965,74.911 R718.2@52.965,77.643 52.808,77.642 47.683,77.642 C702.1@47.131,77.608 v1(45.955,77.608)
  Top Layer w0.35: v1(141.8,67.2) 141.857,67.258 141.959,67.258 142.452,67.75 v1(142.5,67.75) ; v1(141.8,69.4) 141.875,69.4 142.425,68.85 v1(142.5,68.85) ; v1(141.8,70.65) 141.858,70.707 141.96,70.707 142.452,71.2 v1(142.5,71.2) ; v1(141.8,72.85) 141.875,72.85 142.425,72.3 v1(142.5,72.3)
  other v1: 125.867,14.744 126.567,14.744 127.267,14.744 99.003,67.03
VCC_Ethr: C508.2 C515.2 C516.2 FB500.2 L500.2 R500.1 R501.2 R502.2 R503.2 R510.1 R517.2 U500.9 | length 30.6
  Top Layer w0.3: C508.2@138.188,8.723 138.488,8.423 U500.9@140.778,8.423
  Top Layer w0.335: R517.2@127.426,3.499 v1(128.357,3.498) ; v1@133.313,7.823 R502.2@134.243,7.823 ; R501.2@134.218,5.272 v1(135.598,5.272) 136.503,5.272 R500.1@136.653,5.122 ; R503.2@134.243,11.797 v1(134.243,12.522) ; v1(137.5,8.1) 137.56,8.16 137.651,8.16 138.188,8.698 C508.2@138.188,8.723
  Top Layer w0.5: v1(142.855,1.397) R510.1@142.855,3.29
  Bottom Layer w0.5: v1(112.315,12.543) 113.244,11.614 120.513,11.614 124.42,7.707 128.328,3.799 128.328,3.527 v1(128.357,3.498)
  other v1: 133.311,7.824 112.315,13.243 112.315,13.943 112.315,14.643
VDD_BUCK: C412.2 C413.2 C420.1 L401.2 U402.15 U402.32 | length 31.9
  Top Layer w0.2: C420.1@23.844,48.362 23.894,48.695 U402.15@23.894,50.237 ; U402.32@28.294,53.837 29.424,53.837 30.26,54.673 32.38,54.673 v1(32.744,55.037)
  Top Layer w0.335: v1(34.994,50.387) 34.22,50.387 33.778,50.83 L401.2@33.77,50.837 33.776,50.844 34.27,51.337 v1(34.994,51.337)
  Top Layer w0.5: v1(23.294,47.687) 23.319,47.687 23.919,48.287 C420.1@23.944,48.287 ; L401.2@33.77,50.887 33.776,50.844 L401.2@33.776,50.838 ; L401.2@33.778,50.83 33.887,50.034 C413.2@33.887,46.937
  Bottom Layer w0.5: v1(23.294,47.687) 28.444,47.687 31.144,50.387 v1(34.994,50.387) ; v1@32.744,54.997 32.744,53.587 v1(34.994,51.337)
VDD_MCU: C202.1 C207.2 C208.2 C209.2 C210.2 C211.2 C212.2 C213.2 C214.2 C215.2 C216.2 C217.2 C218.2 C219.2 C609.1 C705.2 C706.2 D200.1 FB200.2 J700.1 L700.2 R102.2 R201.1 R300.1 R301.1 R402.2 R700.2 R701.2 R702.2 R703.2 R704.2 R705.2 R706.2 R707.2 R716.2 R717.2 R719.2 TP201.1 TP203.1 TP700.1 U601.16 U701.5 | length 193.8
  Top Layer w0.2: C609.1@24.35,32.27 27.202,32.27 27.56,32.628 U601.16@27.56,33.17
  Top Layer w0.3: C609.1@24.35,32.27 v1@24.35,33.309 ; C207.2@57.95,29.55 58.05,29.45 59.4,29.45 C211.2@59.5,29.35 59.66,29.51 59.835,29.51 60.174,29.85 61.362,29.85 ; v1@58.55,13.055 58.79,12.815 C212.2@58.79,12.56 ; C212.2@58.95,12.4 59.825,12.4 60.774,13.35 61.362,13.35 ; v1@59.25,17.695 59.49,17.935 C219.2@59.49,18.19 ; C218.2@59.49,23.51 59.625,23.51 59.625,24.075 v1(59.6,24.1) ; C219.2@59.65,18.35 61.362,18.35 ; C218.2@59.65,23.35 61.362,23.35 ; 66.35,32.838 66.35,33.911 C209.2@66.85,34.411 ; C209.2@67.01,34.571 67.265,34.571 v1@67.505,34.811 ; C213.2@68.85,9.65 68.85,11.362 ; C213.2@69.01,9.49 69.265,9.49 v1@69.505,9.25 ; v1@72.195,34.95 72.435,34.71 C217.2@72.69,34.71 ; 72.85,32.838 C217.2@72.85,34.55 ; C214.2@74.35,9.65 74.35,11.362 ; C214.2@74.51,9.49 74.765,9.49 v1@75.005,9.25 ; 79.85,11.362 79.85,10.538 80.348,10.04 82.349,10.04 82.399,10.09 C202.1@82.449,10.04 82.609,10.2 82.609,10.455 82.849,10.695 v1(82.849,10.79) 82.849,10.885 82.609,11.125 82.609,11.38 C208.2@82.449,11.54 81.547,10.638 80.986,10.638 80.85,10.774 80.85,11.362 ; 82.838,19.35 C210.2@84.55,19.35 ; 82.838,24.35 C216.2@84.55,24.35 ; 82.838,30.85 83.606,30.85 84.556,31.8 C215.2@85.25,31.8 85.41,31.64 85.41,31.385 85.605,31.19 85.65,31.19 85.79,31.05 88.034,31.05 TP201.1@89.65,31.05 ; C210.2@84.71,19.19 84.71,18.935 v1@84.95,18.695 ; C216.2@84.71,24.51 84.71,24.765 v1@84.95,25.005 ; J700.1@90.162,42.294 v1(91.3,42.294) ; v1@108.76,30.729 109,30.969 109,31.225 ; v1(114.587,23.7) R301.1@115.375,23.7 ; R300.1@117.95,23.7 117.966,23.716 118.816,23.716 v1(118.833,23.732)
  Top Layer w0.335: v1@17.664,58.887 R402.2@18.594,58.887 ; TP203.1@46.174,64.8 C706.2@47.85,64.8 ; v1(49.829,63.415) 49.829,62.171 TP700.1@50.9,61.1 ; v1(51.833,3.564) R704.2@52.765,3.562 ; v1(51.833,4.838) R705.2@52.765,4.837 ; v1(51.833,6.088) R706.2@52.765,6.087 ; v1(51.833,7.46) R707.2@52.765,7.458 ; v1(56.932,30.025) 56.943,30.014 57.461,30.014 58.025,29.45 C207.2@58.05,29.45 ; v1(57.95,37.611) v1(57.95,38.3) ; v1(57.95,38.989) v1(57.95,38.3) ; R719.2@58.558,77.023 v1(59.49,77.022) ; FB200.2@59,38.3 v1(57.95,38.3) ; v1@79.6,6.695 R201.1@79.6,7.425 ; R717.2@80.85,38.25 v1(80.85,38.989) ; U701.5@87.05,39.15 v1(87.789,39.15) ; R702.2@88.05,14.975 v1@88.05,15.905 ; R703.2@89.55,14.975 v1@89.55,15.905 ; R701.2@91.051,14.975 v1@91.051,15.905 ; v1@92.405,18.02 92.405,18.95 ; R700.2@92.551,14.975 v1@92.551,15.905 ; v1@92.551,15.909 v1(92.552,15.907) ; v1@135.7,45.45 R102.2@135.7,46.249
  Top Layer w0.5: D200.1@77.3,47.611 v1(77.3,48.525) 78.225,49.45 R716.2@79.065,49.45
  Bottom Layer w0.335: v1(17.662,58.889) 20.185,61.412 20.185,63.935 22.45,66.2 44.944,66.2 v1(47.729,63.415)
  Bottom Layer w0.5: v1(49.129,63.415) 49.129,70.179 55.972,77.022 v1(59.49,77.022) ; v1(104.5,40.05) 130.3,40.05 v1(135.697,45.448) 137.5,47.25 137.5,61.09 147.329,70.92
  other v1: 79.598,6.693 69.6,9.25 75.1,9.25 58.55,13.15 88.052,15.907 89.552,15.907 91.052,15.907 59.25,17.6 92.407,18.018 84.95,18.6 84.95,25.1 108.76,30.635 85.65,31.05 24.345,33.314 67.6,34.811 72.1,34.95 48.429,63.415
VDDA: C220.2 C221.2 C222.2 FB200.1 FB201.1 | length 8.7
  Top Layer w0.3: C222.2@62.5,34.654 63.801,34.654 64.85,33.606 64.85,32.838
  Top Layer w0.4: C222.2@62.5,34.654 C221.2@62.5,35.899 FB201.1@62.5,38.3
  Top Layer w0.6: FB200.1@61,38.3 FB201.1@62.5,38.3
VIN: D100.2 D101.2 D103.2 J100.1 J100.2 R206.2 | length 60.3
  Top Layer w0.3: v1(67.925,67.196) 68.873,67.196 D103.2@68.923,67.246 ; v1(67.925,68.296) 68.959,68.296 D103.2@68.973,68.31 ; v1(67.925,69.396) 68.972,69.396 D103.2@68.973,69.395 ; v1(97.7,72.25) 98.648,72.25 D101.2@98.698,72.3 ; v1(97.7,73.35) 98.735,73.35 D101.2@98.748,73.364 ; v1(97.7,74.45) 98.747,74.45 D101.2@98.748,74.448 ; D100.2@140.752,74.951 140.753,74.95 v1(141.8,74.95) ; D100.2@140.752,76.036 140.765,76.05 v1(141.8,76.05) ; D100.2@140.802,77.1 140.852,77.15 v1(141.8,77.15)
  Top Layer w0.35: v1(67.225,67.746) 67.3,67.746 67.85,67.196 v1(67.925,67.196) ; v1(67.225,68.846) 67.273,68.846 67.765,69.339 67.867,69.339 v1(67.925,69.396) ; v1(97,72.8) 97.075,72.8 97.625,72.25 v1(97.7,72.25) ; v1(97,73.9) 97.048,73.9 97.541,74.393 97.643,74.393 v1(97.7,74.45) ; v1(141.8,74.95) 141.858,75.007 141.96,75.007 142.452,75.5 v1(142.5,75.5) ; v1(141.8,77.15) 141.875,77.15 142.425,76.6 v1(142.5,76.6)
  Top Layer w0.5: R206.2@54.7,27.675 54.7,32.014 56.818,34.132 56.818,39.948 67.925,51.055 v1(67.925,67.196) ; D101.2@99.45,72.95 D101.2@99.45,73.35
VREF+: C226.2 C227.2 C228.2 FB201.2 | length 9.5
  Top Layer w0.3: FB201.2@62.5,40.3 63.9,40.3 C226.2@64.3,39.9 C227.2@64.3,38.7 C228.2@64.3,37.29 64.3,36.15 65.35,35.1 65.35,32.838
W_Dis: TP601.1 U601.10 | length 39.4
  Top Layer w0.2: U601.10@29.56,31.37 29.56,30.244 v1(30.96,28.844)
  Top Layer w0.335: 32.55,5.125 32.55,5.37 ; v1(32.55,6.321) 32.55,5.37 ; TP601.1@37.7,4.9 37.23,5.37 32.55,5.37
  Bottom Layer w0.335: v1(30.96,28.844) 30.044,28.844 24.7,23.5 24.7,12.684 28.084,9.3 29.571,9.3 v1(32.55,6.321)
W_DISABLE#: U601.11 | length 37.6
  Top Layer w0.2: U601.11@29.56,33.17 29.56,33.69 v1(30.02,34.15)
  Top Layer w0.3: v1@56.818,21.85 v1(56.82,21.85) 61.362,21.85
  Bottom Layer w0.335: v1(30.02,34.15) 39.75,34.15 50,23.9 51.902,23.9 53.952,21.85 v1(56.82,21.85)
WARN: 
WDI: R720.2 TP701.1 U701.4 | length 9.8
  Top Layer w0.3: 79.35,32.838 79.35,33.754 80.006,34.411 81.486,34.411 82.286,35.211 R720.2@82.286,35.311 TP701.1@84.535,35.311 86.499,37.275 U701.4@86.749,37.275
WP:  | length 15.1
  Top Layer w0.3: 82.043,22.85 82.838,22.85
  Top Layer w0.335: v1(81.561,22.85) 82.043,22.85 ; v1(89.45,25.8) 89.45,25.715 89.682,25.482 89.682,25.033 89.865,24.85
  Bottom Layer w0.335: v1(81.561,22.85) 80.85,23.561 80.85,25.65 82,26.8 88.668,26.8 89.39,26.078 89.39,25.86 v1(89.45,25.8)
pads on no net: FD1.Fiducial FD2.Fiducial FD3.Fiducial FD4.Fiducial J100. J101.h1 J101.h2 J500.7 J500.15 J500.16 J700.TH1 J700.TH2 J700.TH3 S100.0 U402.2 U402.3 U402.4 U402.5 U402.6 U402.21 U402.22 U402.23 U402.24 U602.4 U603.1 U603.7

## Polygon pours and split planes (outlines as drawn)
VDD_MCU on POWER "Layer 2" (solid, remove dead copper, pour order 8): 45.014,48.897 45.014,73.097 69.214,48.897 98.464,48.897 119.614,27.747 119.614,23.097 102.414,23.097 96.464,29.047 96.464,-0.003 76.464,-0.003 16.614,-0.003 16.614,34.347 25.364,34.347 35.714,25.697 45.014,25.697
PVDD on POWER "Layer 2" (solid, remove dead copper, pour order 7): 96.464,28.997 102.364,23.097 119.614,23.097 119.614,27.697 98.414,48.897 116.814,48.897 124.964,40.747 124.964,16.297 96.464,16.297
VCC on POWER "Layer 2" (solid, remove dead copper, pour order 4): 82.1,61.3 91.7,70.9 132,70.9 134.7,73.6 142.6,73.6 150.5,65.7 180.014,65.7 180.014,48.747 180.014,33.397 156.864,33.397 141.664,16.297 130.539,16.297 128.164,13.922 124.964,13.922 124.964,16.297 124.964,40.747 116.814,48.897 69.214,48.897 45.014,73.097 10.764,73.097 10.764,79.997 53.8,80 72.5,61.3
+VCC_modem on POWER "Layer 2" (solid, remove dead copper, pour order 9): 45.014,73.097 22.364,73.097 22.364,70.647 35.714,57.297 35.714,44.597 0.014,44.597 0.014,-0.003 16.614,-0.003 16.614,34.347 25.298,34.347 25.364,34.347 35.714,25.697 45.014,25.697
VIN on POWER "Layer 2" (solid, remove dead copper, pour order 3): 180.014,79.997 180.014,65.7 150.5,65.7 142.6,73.6 134.7,73.6 132,70.9 91.7,70.9 82.1,61.3 72.5,61.3 62.917,70.947 53.8,80
NetC502_2 on POWER "Layer 2" (solid, remove dead copper, pour order 5): 113.364,16.297 120.164,9.497 130.186,9.497 133.585,12.896 136.779,12.896 145.814,3.861 145.814,-0.003 180.014,-0.003 180.014,33.397 157.121,33.397 141.664,16.297
VCC_Ethr on POWER "Layer 2" (solid, remove dead copper, pour order 6): 139.065,12.896 116.765,12.896 113.364,16.297 96.464,16.297 96.464,-0.003 145.814,-0.003 145.814,6.147
VBAT_nRF on POWER "Layer 2" (solid, remove dead copper, pour order 10): 0.014,79.997 10.764,79.997 10.764,73.097 22.364,73.097 22.364,70.647 35.714,57.297 35.714,44.597 22.364,44.597 0.014,44.597
GND on GND 2 "Layer 5" (solid, remove dead copper, pour order 0): 0,0 0,80 180,80 180,0
GND on Bottom Layer "Layer 2" (solid, remove dead copper, pour order 17): 0,0 0,80 180,80 180,0
GND on Signal 1 "Layer 2" (solid, remove dead copper, pour order 18): 0,0 0,80 180,80 180,0
GND on GND 1 "Layer 2" (solid, remove dead copper, pour order 21): 0,0 0,80 180,80 180,0
GND on Top Layer "Layer 2" (solid, remove dead copper, pour order 20): 0,0 0,80 180,80 180,0

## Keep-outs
Top Layer:
  lines w0.2: 13.609,32.418 14.7,32.418 ; 19.031,53.463 19.031,55.012 ; 25.144,48.537 25.144,46.938 26.144,45.937 27.588,45.937 28.094,46.443 28.094,48.088 27.288,48.894 26.394,48.894 ; 38.355,7.415 39.445,7.415 ; 40.476,69.385 41.4,69.385 ; 68.35,33.76 67.6,34.51 67.6,36.2 66.7,37.1 66.7,38.9 67.3,39.5 72.523,39.5 73.1,38.923 73.1,37.35 72.3,36.55 72.3,35.888 70.983,34.571 ; 75.7,35.211 74.6,36.311 74.6,43.1 75.4,43.9 78.4,43.9 79.586,42.714 79.586,36.801 78.225,35.44 ; 78,70.1 78,72.874 ; 141.625,11.009 140.732,11.902 139.602,11.902 139.002,12.502 139.002,15.602 139.76,16.36 144.745,16.36 145.602,15.503 145.602,14.548 145.602,12.275 144.994,11.668
Signal 1:
  rectangle: 80.3,66.01 93.4,79.01
  rectangle: 96.7,40.15 102.7,46.15
  rectangle: 2.958,65.381 10.658,73.131
  rectangle: 31.8,66.6 38.7,73.15
  rectangle: 50.758,62.581 58.458,70.331
  rectangle: 111.5,2.151 119.2,9.9
GND 1:
  lines w0.2: 25.144,48.537 25.144,46.938 26.144,45.937 27.588,45.937 28.094,46.443 28.094,48.088 27.288,48.894 26.394,48.894 ; 68.35,33.76 67.6,34.51 67.6,36.2 66.7,37.1 66.7,38.9 67.3,39.5 72.523,39.5 73.1,38.923 73.1,37.35 72.3,36.55 72.3,35.888 70.983,34.571 ; 75.7,35.211 74.6,36.311 74.6,43.1 75.4,43.9 78.4,43.9 79.586,42.714 79.586,36.801 78.225,35.44 ; 141.623,11.008 140.731,11.9 139.6,11.9 139,12.5 139,15.6 139.758,16.358 144.743,16.358 145.6,15.501 145.6,14.546 145.6,12.274 144.993,11.666
Bottom Layer:
  rectangle: 80.3,66.01 93.4,79.01
  rectangle: 96.7,40.15 102.7,46.15
  rectangle: 2.958,65.381 10.658,73.131
  rectangle: 31.8,66.6 38.7,73.15
  rectangle: 50.758,62.581 58.458,70.331
  rectangle: 111.5,2.151 119.2,9.9
  lines w0.2: 22.555,37.3 23.645,37.3 ; 68.8,45.94 68.8,46.7 ; 156.9,59.2 156.9,60 ; 172.5,38.8 172.5,39.6 ; 172.5,47.655 172.5,48.745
